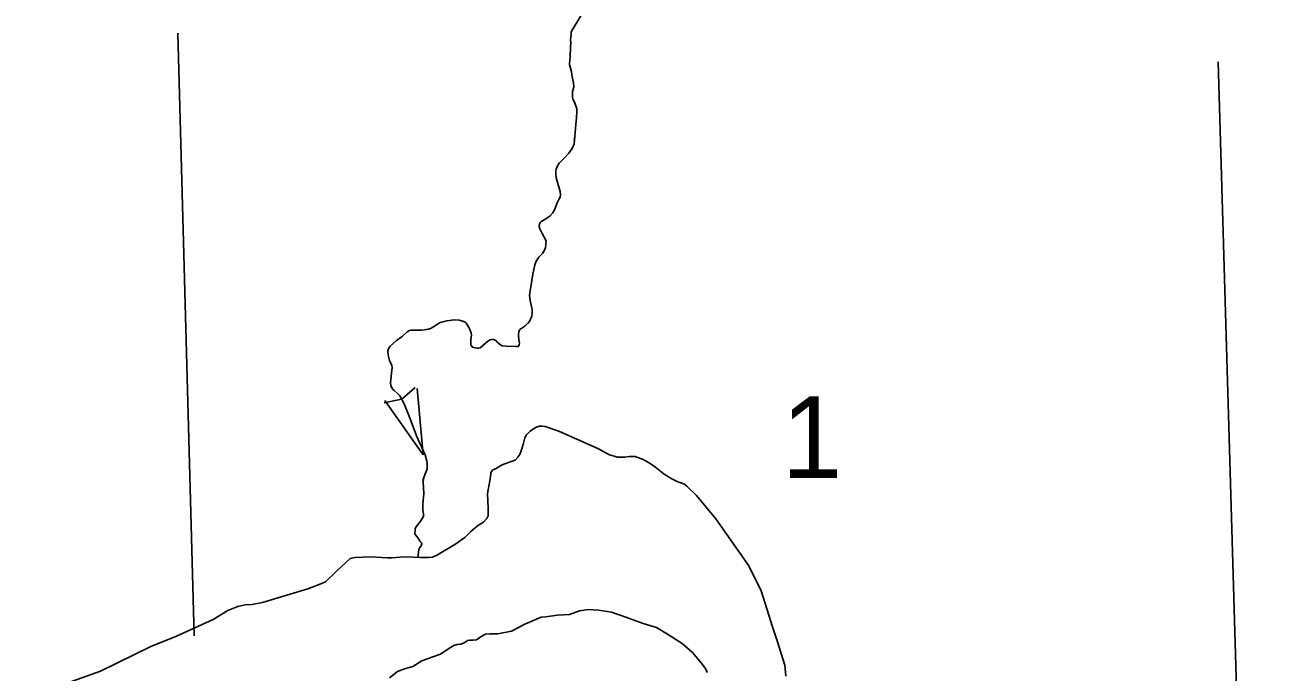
# Model space of a CAD drawing. Extents: x 1720274 to 1751788, y 372074 to 391887.
# Drawn here: x 1740069 to 1741086, y 376671 to 377198 of the extents above; entities that cross this region are included whole.
import ezdxf

# ---------------------------------------------------------------- set-up
doc = ezdxf.new("R2010")
doc.units = 0
for name, color, linetype in [('Level 2', 7, 'Continuous'), ('Level 35', 7, 'Continuous'), ('Level 43', 7, 'Continuous'), ('Level 5', 7, 'Continuous')]:
    doc.layers.add(name, color=color, linetype=linetype)

msp = doc.modelspace()

# ---------------------------------------------------------------- linework, layer by layer
at = {"layer": 'Level 2'}
msp.add_lwpolyline([(1741041.6, 377168), (1741063.2, 376434.6), (1741062.9, 376421.4), (1741085.5, 375618.3)], dxfattribs=at)
at = {"layer": 'Level 35'}
for points in [[(1740689.3, 376667.5), (1740688.6, 376676.5), (1740682.4, 376695.7), (1740678.5, 376707.9), (1740669.1, 376737.2), (1740659, 376757.4), (1740632.3, 376795.7), (1740616.6, 376814.8), (1740608.6, 376822.5), (1740606.2, 376824.2), (1740601.3, 376826), (1740596.4, 376828.4), (1740590.1, 376832.2), (1740583.2, 376837.5), (1740578.7, 376840.9), (1740573.1, 376844.1), (1740566.5, 376846.5), (1740561.6, 376846.5), (1740558.2, 376846.1), (1740555.1, 376846.1), (1740551.8, 376846.1), (1740544.9, 376848.3), (1740536.7, 376852.8), (1740504.4, 376867.3), (1740493.2, 376871), (1740490.7, 376871.3), (1740488.5, 376871.3), (1740485.2, 376870.1), (1740480.9, 376867.3), (1740477.8, 376864.1), (1740476.6, 376861.8), (1740475.2, 376856.4), (1740473.6, 376851.2), (1740472.6, 376848.1), (1740471, 376846.1), (1740468.8, 376843.6), (1740465.5, 376842.4), (1740458.1, 376839.8), (1740452.7, 376836.4), (1740450.6, 376835.8), (1740448.9, 376833.4), (1740448.9, 376832.2), (1740448, 376826.7), (1740446.1, 376816.5), (1740446.8, 376804.3), (1740446.8, 376798.3), (1740445.6, 376796), (1740442.8, 376793.1), (1740438, 376790), (1740432.6, 376785.6), (1740427.6, 376780.6), (1740419.5, 376774.9), (1740405.5, 376766.6), (1740401.3, 376764.5), (1740398.1, 376764.2), (1740395.1, 376764.2), (1740391.5, 376764.2), (1740385.8, 376764.5), (1740379.9, 376764.9), (1740374.9, 376764.7), (1740368, 376764), (1740364.5, 376764), (1740360, 376764.4), (1740351, 376764.9), (1740344.6, 376764.5), (1740338.1, 376764.4), (1740334.1, 376763.5), (1740330.4, 376760)], [(1740330.4, 376760), (1740323, 376753.1), (1740314.2, 376744.5), (1740309, 376742.2), (1740299.7, 376738.7), (1740262.8, 376727.7), (1740254.4, 376726.1), (1740248.7, 376725.8), (1740242.6, 376724.4), (1740234.5, 376721.1), (1740222.7, 376713.8), (1740192.8, 376700.3), (1740171.9, 376691.8), (1740130.7, 376671.6), (1740069.2, 376649.6)], [(1740437.1, 376697.3), (1740441, 376700), (1740444.4, 376701.9), (1740448.1, 376702.2), (1740454.5, 376702.2), (1740465.6, 376704.3), (1740476.7, 376710.1), (1740489.9, 376715.6), (1740493.7, 376715.9), (1740503.3, 376717.2), (1740512.9, 376717.9), (1740521.1, 376720.9), (1740528.5, 376721.9), (1740536.5, 376721.5), (1740547.1, 376719.8), (1740558.9, 376715.6), (1740573, 376710.6), (1740583.9, 376707.3), (1740592.9, 376701.9), (1740604.8, 376694.2), (1740613.5, 376686.6), (1740621.5, 376677), (1740624.1, 376673.4), (1740625.1, 376670.5)], [(1740366.4, 376666.2), (1740372.8, 376671.3), (1740378.4, 376673.5), (1740385.3, 376675.5), (1740392.7, 376680.1), (1740401.7, 376683.3), (1740407.8, 376685.6), (1740414.5, 376690.2), (1740418.8, 376692.7), (1740421.5, 376693.3), (1740424.2, 376693.6), (1740426.6, 376694.5), (1740428.5, 376695.5), (1740429.9, 376696.6), (1740431.8, 376696.9), (1740434.4, 376696.9), (1740437.1, 376697.3)]]:
    msp.add_lwpolyline(points, dxfattribs=at)
at = {"layer": 'Level 43'}
for p, q in [((1740362, 376890.3), (1740376.1, 376893.2)), ((1740387.1, 376902.9), (1740376.3, 376893.3)), ((1740393.8, 376848), (1740388.9, 376902)), ((1740393.8, 376848), (1740362.6, 376892.3))]:
    msp.add_line(p, q, dxfattribs=at)
for points in [[(1740528.6, 377226.6), (1740528.5, 377224.5), (1740527.5, 377218.3), (1740524.4, 377211.2), (1740522.3, 377205.6), (1740514.3, 377192.5), (1740514.2, 377190.5), (1740513.9, 377186.1), (1740513.9, 377186)], [(1740522.3, 377205.6), (1740514.3, 377192.5), (1740514.2, 377190.5), (1740513.9, 377186.1), (1740514, 377183.6), (1740513.9, 377179.9), (1740513.6, 377172.2), (1740513, 377166.7), (1740513.1, 377165.5), (1740514.7, 377159.9), (1740515.2, 377155.8), (1740516.2, 377150.9), (1740516.4, 377147.3), (1740515.4, 377143.9), (1740515.3, 377141.1), (1740515.3, 377139.2), (1740515.7, 377137.6), (1740516.8, 377135.8), (1740518.9, 377130), (1740518.9, 377127.6), (1740518.8, 377122.6), (1740518, 377117.1), (1740517.2, 377107.3), (1740516.7, 377101.3), (1740515.1, 377097.4), (1740512.5, 377093.6), (1740508.3, 377089.3), (1740504.6, 377085.6), (1740503.2, 377083.4), (1740502, 377080.6), (1740501.9, 377079.1), (1740501.8, 377077), (1740502.1, 377073.7), (1740503, 377070.8), (1740505.4, 377062.5), (1740505.6, 377059.7), (1740505.4, 377057.7), (1740504.2, 377055.8), (1740502.9, 377053.3)], [(1740513.2, 377165.2), (1740514.7, 377159.9), (1740515.2, 377155.8), (1740516.2, 377150.9), (1740516.4, 377147.3), (1740515.4, 377143.9), (1740515.3, 377141.1), (1740515.3, 377139.2), (1740515.7, 377137.6), (1740516.8, 377135.8), (1740517.1, 377134.8)], [(1740517.1, 377134.8), (1740518.9, 377130), (1740518.9, 377127.6), (1740518.8, 377122.6), (1740518, 377117.1), (1740517.2, 377107.3), (1740516.9, 377104)], [(1740505.9, 377086.9), (1740504.6, 377085.6), (1740503.2, 377083.4), (1740502, 377080.6), (1740501.9, 377079.1), (1740501.8, 377077), (1740502.1, 377073.7), (1740503, 377070.8), (1740505.4, 377062.5), (1740505.6, 377059.7), (1740505.4, 377057.7), (1740504.2, 377055.8), (1740502.9, 377053.3), (1740501.9, 377050.3), (1740500.8, 377047.5), (1740499.2, 377044.9), (1740496.9, 377042.4), (1740492.3, 377039.4), (1740489.5, 377037.6), (1740488.7, 377036.5), (1740488.3, 377034.8), (1740488.3, 377033.9), (1740488.6, 377032.8)], [(1740502.9, 377053.3), (1740501.9, 377050.3), (1740500.8, 377047.5), (1740499.2, 377044.9), (1740496.9, 377042.4), (1740492.3, 377039.4), (1740489.5, 377037.6), (1740488.7, 377036.5), (1740488.3, 377034.8), (1740488.3, 377033.9), (1740488.8, 377032.1), (1740490.6, 377028.3), (1740493.5, 377023.2), (1740493.9, 377021.6), (1740493.8, 377019.4), (1740493.3, 377016.4), (1740491.2, 377012.3), (1740487.9, 377009), (1740485.7, 377005.8), (1740484.6, 377002.6), (1740483, 376995.2), (1740480.8, 376981.5), (1740480.4, 376977.6), (1740480.8, 376973.6), (1740482.5, 376966.4), (1740482.6, 376964), (1740482.2, 376960.9), (1740480.4, 376956.6), (1740476.5, 376952.6), (1740472.5, 376950.1), (1740471.7, 376948.3), (1740471.4, 376945.8), (1740471.8, 376941.6), (1740472.2, 376938.8), (1740472, 376937.7), (1740471.7, 376936.8), (1740470.9, 376936.3), (1740469.2, 376936.3), (1740461.7, 376936.4), (1740458.2, 376936.8), (1740456.8, 376937.5), (1740455.4, 376938.5), (1740454.1, 376939.8), (1740452.9, 376941), (1740451.9, 376941.6), (1740451, 376941.8), (1740449.7, 376941.8), (1740448.2, 376941.7), (1740446.3, 376940.4), (1740442.4, 376936.9), (1740440.2, 376935.1), (1740438.8, 376934.7), (1740437.9, 376934.7), (1740436, 376935), (1740433.9, 376935.7), (1740433.2, 376936.7), (1740432.6, 376937.6), (1740432.5, 376938.3), (1740432.5, 376940), (1740432.6, 376941.6), (1740433, 376945.7), (1740432.8, 376947.1), (1740432.1, 376949.4), (1740430.9, 376951.6), (1740429.5, 376954.2), (1740428.1, 376955.6), (1740426.1, 376956.8), (1740423.1, 376957.7), (1740419.3, 376958), (1740413, 376957.2), (1740407.7, 376955.6), (1740405.3, 376954.3), (1740402.1, 376952.2), (1740399.7, 376950.7), (1740398, 376950.2), (1740392.5, 376949.6), (1740384.1, 376949.6), (1740382.5, 376949.3), (1740380.6, 376948), (1740376.6, 376944.4), (1740371.9, 376941.1), (1740366.7, 376936.5), (1740365.4, 376934.2), (1740365, 376932.6), (1740365.1, 376929), (1740366.2, 376924.7), (1740368.3, 376920.7), (1740368.5, 376919), (1740368, 376914.4), (1740367.1, 376906.5), (1740367.4, 376904.4), (1740368.7, 376901.5), (1740370, 376900.2), (1740372.4, 376898.2), (1740374.8, 376896.1), (1740378.1, 376889.5), (1740383.1, 376877.2), (1740388.2, 376863.3), (1740395.4, 376847.8), (1740396.9, 376841.8), (1740397, 376838.7)], [(1740491.9, 377013.6), (1740491.2, 377012.3), (1740487.9, 377009), (1740485.7, 377005.8), (1740484.6, 377002.6), (1740483, 376995.2), (1740480.8, 376981.5), (1740480.4, 376977.6), (1740480.8, 376973.6), (1740482.5, 376966.4), (1740482.6, 376964), (1740482.2, 376960.9), (1740480.4, 376956.6), (1740478.9, 376955)], [(1740410.2, 376956.3), (1740407.7, 376955.6), (1740405.3, 376954.3), (1740402.1, 376952.2), (1740399.7, 376950.7), (1740398, 376950.2), (1740392.5, 376949.6), (1740384.1, 376949.6), (1740382.5, 376949.3), (1740380.6, 376948), (1740376.6, 376944.4), (1740371.9, 376941.1), (1740366.7, 376936.5), (1740365.4, 376934.2), (1740365, 376932.6), (1740365.1, 376929), (1740366.2, 376924.7), (1740366.5, 376924.2)], [(1740472, 376937.6), (1740471.7, 376936.8), (1740470.9, 376936.3), (1740469.2, 376936.3), (1740461.7, 376936.4), (1740458.2, 376936.8), (1740456.8, 376937.5), (1740455.4, 376938.5), (1740454.1, 376939.8), (1740452.9, 376941), (1740451.9, 376941.6), (1740451, 376941.8), (1740449.7, 376941.8), (1740448.2, 376941.7), (1740446.3, 376940.4), (1740442.4, 376936.9), (1740440.2, 376935.1), (1740438.8, 376934.7), (1740437.9, 376934.7), (1740436, 376935), (1740433.9, 376935.7), (1740433.2, 376936.7), (1740432.6, 376937.6), (1740432.5, 376938.3), (1740432.5, 376940), (1740432.6, 376941.6), (1740433, 376945.7), (1740432.8, 376947.1), (1740432.1, 376949.4), (1740430.9, 376951.6), (1740429.6, 376953.9)], [(1740367.6, 376903.9), (1740368.7, 376901.5), (1740370, 376900.2), (1740372.4, 376898.2), (1740374.8, 376896.1), (1740378.1, 376889.5), (1740383.1, 376877.2), (1740388.2, 376863.3), (1740395.1, 376848.5)], [(1740397, 376838.7), (1740397, 376836.3), (1740395.3, 376832.4), (1740393.9, 376828.7), (1740393.6, 376825.6), (1740394.2, 376816.4), (1740393.4, 376807.8), (1740393.4, 376802.9), (1740394.1, 376799.9), (1740393.9, 376797.6), (1740392.1, 376794.7), (1740389.8, 376791.6), (1740387.8, 376789.1), (1740387.2, 376787.7), (1740387.1, 376786.4), (1740386.8, 376784.1)], [(1740393.8, 376828.5), (1740393.6, 376825.6), (1740394.2, 376816.4), (1740393.4, 376807.8), (1740393.4, 376802.9), (1740394.1, 376799.9), (1740393.9, 376797.6), (1740393.7, 376797.4)], [(1740393.7, 376797.4), (1740392.1, 376794.7), (1740389.8, 376791.6), (1740387.8, 376789.1), (1740387.2, 376787.7), (1740387.1, 376786.4), (1740386.8, 376784.1)], [(1740386.8, 376784.1), (1740387, 376783.6), (1740387.6, 376782.7), (1740388.6, 376781.4), (1740390.1, 376779.3), (1740391.4, 376777.2), (1740392.3, 376776.3), (1740392.6, 376775.3), (1740392.2, 376773.7), (1740390.9, 376772.4), (1740390.2, 376770.7), (1740390, 376768.5), (1740389.6, 376766.4), (1740389.3, 376764.5)]]:
    msp.add_lwpolyline(points, dxfattribs=at)
at = {"layer": 'Level 5'}
msp.add_lwpolyline([(1740193.8, 377191.5), (1740207.1, 376700.5)], dxfattribs=at)

# ---------------------------------------------------------------- texts
msp.add_text('1', height=66.7, dxfattribs=at).set_placement((1740685.8, 376829))

doc.saveas('drawing.dxf')
